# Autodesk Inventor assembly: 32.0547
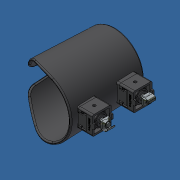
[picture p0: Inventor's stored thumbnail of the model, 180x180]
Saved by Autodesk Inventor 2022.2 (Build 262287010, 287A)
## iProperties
Created: 2014-10
Part Number: 32.0547
Document SubType Name: Assembly
Designer: Admin
Description: CUP HOLDER
Translation Standard: STEP AP203
FileName: C:\Temp\320547_0.stp
PreProcessor: Autodesk Inventor 2014
PostProcessor: Build: 160, Release: 2012 RTM - Date: Tue 03/01/2011
Sent Units: millimeter
Uncertainty: 0.01
Author: Admin
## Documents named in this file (6)
- L:\INVENTOR LIBRARIES\PARTS LIBRARY\WORKSTATION\32.0547 CUP HOLDER.iam
- L:\INVENTOR LIBRARIES\PARTS LIBRARY\FASTENING ELEMENTS\SET SCREWS\SET SCREW M5X25 FLAT POINT DIN 913.ipt
- L:\INVENTOR LIBRARIES\PARTS LIBRARY\FASTENING ELEMENTS\SCREWS CAP\21.1200 M8X16.ipt
- L:\INVENTOR LIBRARIES\PARTS LIBRARY\FASTENING ELEMENTS\NUTS\21.1351_2 M8 SQUARE NUT POS FXG.ipt
- L:\INVENTOR LIBRARIES\PARTS LIBRARY\WORKSTATION\SUBCOMPONENTS\32.0547 CUP HOLDER MOUNTING BLOCK.ipt
- L:\INVENTOR LIBRARIES\PARTS LIBRARY\WORKSTATION\SUBCOMPONENTS\32.0547 CUP HOLDER.ipt
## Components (9 placed, 5 different names)
1. 32.0547 CUP HOLDER:1 — Mate:6, Mate:8, Mate:9, Mate:11, Mate:12
2. 32.0547 CUP HOLDER MOUNTING BLOCK:1 — Mate:4, Flush:1, Insert:1, Angle:1, Mate:6, Mate:7, Mate:8, Mate:9, Flush:3
3. 32.0547 CUP HOLDER MOUNTING BLOCK:2 — Mate:10, Flush:2, Insert:2, Insert:3, Angle:2, Mate:11, Flush:3, Mate:12
4. 21.1200 M8 x 16:1 — Insert:1, Mate:5
5. 21.1200 M8 x 16:2 — Insert:2
6. 21.1351_2 M8 SQUARE NUT POS FXG:1 — Insert:3, Angle:2
7. 21.1351_2 M8 SQUARE NUT POS FXG:2 — Mate:5, Angle:1, Mate:7
8. SET SCREW M5X25 FLAT POINT DIN 913:1 — Mate:10, Flush:2
9. SET SCREW M5X25 FLAT POINT DIN 913:2 — Mate:4, Flush:1
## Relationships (17: Mate 9, Flush 3, Insert 3, Angle 2)
- Mate:4: 32.0547 CUP HOLDER MOUNTING BLOCK:1 ↔ SET SCREW M5X25 FLAT POINT DIN 913:2
- Flush:1: 32.0547 CUP HOLDER MOUNTING BLOCK:1 ↔ SET SCREW M5X25 FLAT POINT DIN 913:2
- Insert:1: 32.0547 CUP HOLDER MOUNTING BLOCK:1 ↔ 21.1200 M8 x 16:1
- Mate:5: 21.1200 M8 x 16:1 ↔ 21.1351_2 M8 SQUARE NUT POS FXG:2
- Angle:1: 32.0547 CUP HOLDER MOUNTING BLOCK:1 ↔ 21.1351_2 M8 SQUARE NUT POS FXG:2
- Mate:6: 32.0547 CUP HOLDER:1 ↔ 32.0547 CUP HOLDER MOUNTING BLOCK:1
- Mate:7: 32.0547 CUP HOLDER MOUNTING BLOCK:1 ↔ 21.1351_2 M8 SQUARE NUT POS FXG:2
- Mate:8: 32.0547 CUP HOLDER:1 ↔ 32.0547 CUP HOLDER MOUNTING BLOCK:1
- Mate:9: 32.0547 CUP HOLDER:1 ↔ 32.0547 CUP HOLDER MOUNTING BLOCK:1
- Mate:10: 32.0547 CUP HOLDER MOUNTING BLOCK:2 ↔ SET SCREW M5X25 FLAT POINT DIN 913:1
- Flush:2: 32.0547 CUP HOLDER MOUNTING BLOCK:2 ↔ SET SCREW M5X25 FLAT POINT DIN 913:1
- Insert:2: 32.0547 CUP HOLDER MOUNTING BLOCK:2 ↔ 21.1200 M8 x 16:2
- Insert:3: 32.0547 CUP HOLDER MOUNTING BLOCK:2 ↔ 21.1351_2 M8 SQUARE NUT POS FXG:1
- Angle:2: 32.0547 CUP HOLDER MOUNTING BLOCK:2 ↔ 21.1351_2 M8 SQUARE NUT POS FXG:1
- Mate:11: 32.0547 CUP HOLDER:1 ↔ 32.0547 CUP HOLDER MOUNTING BLOCK:2
- Flush:3: 32.0547 CUP HOLDER MOUNTING BLOCK:1 ↔ 32.0547 CUP HOLDER MOUNTING BLOCK:2
- Mate:12: 32.0547 CUP HOLDER:1 ↔ 32.0547 CUP HOLDER MOUNTING BLOCK:2
